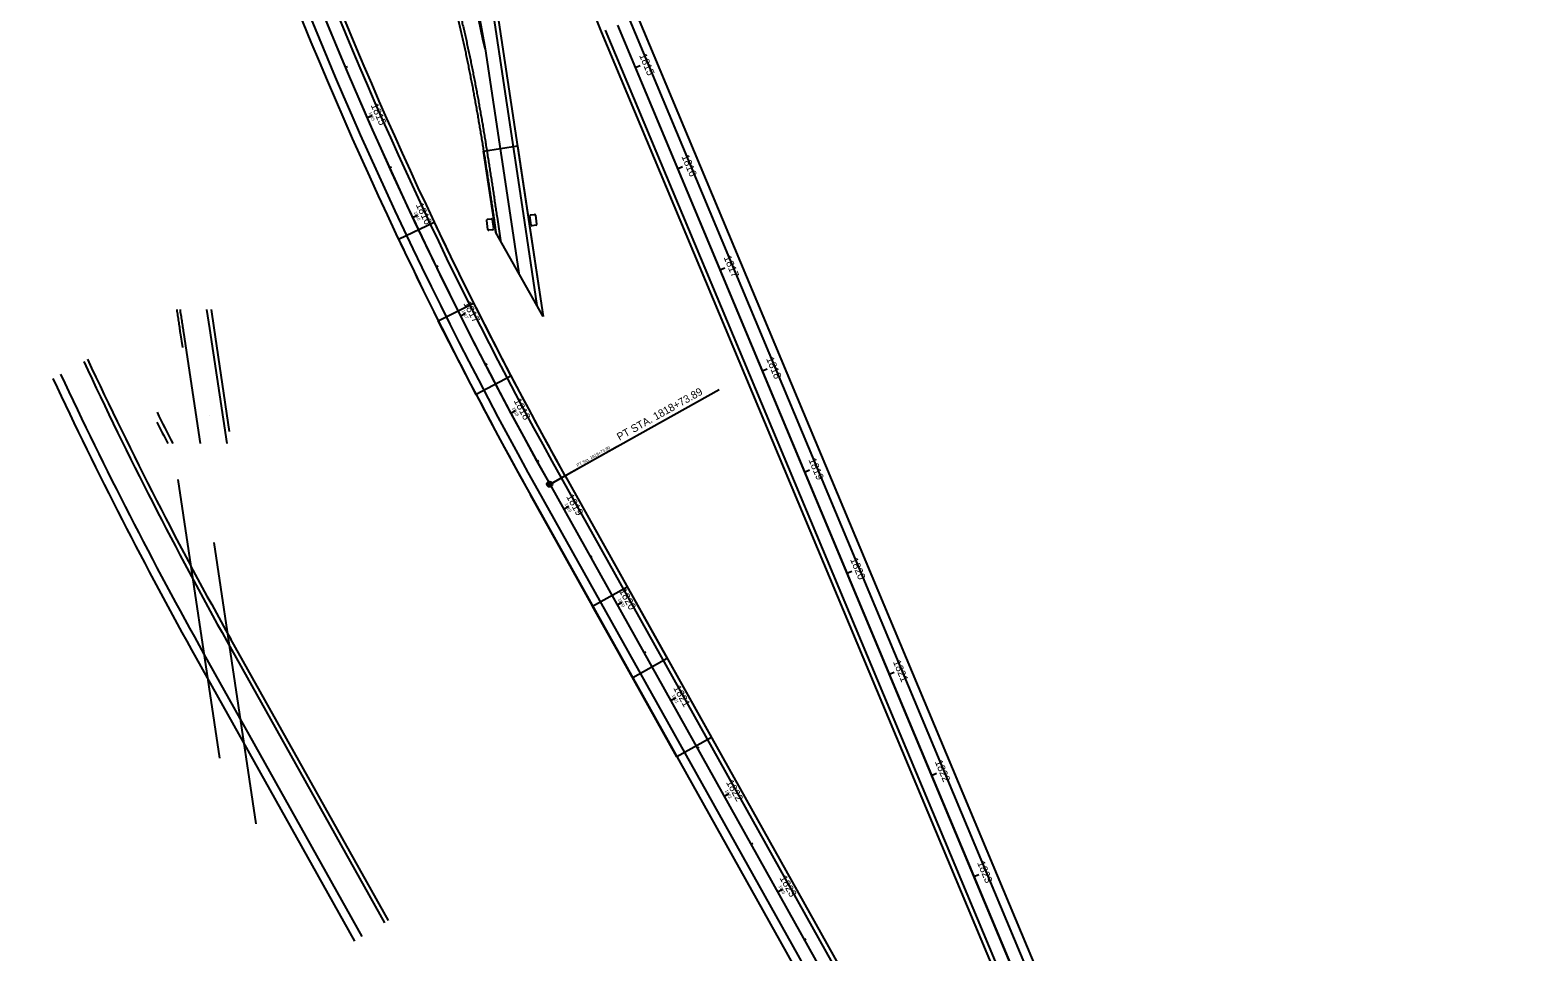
# Model space of a CAD drawing. Extents: x 8527 to 36635, y 12099 to 39012.
# Drawn here: x 20646 to 22022, y 33939 to 34779 of the extents above; entities that cross this region are included whole.
import ezdxf

# ---------------------------------------------------------------- set-up
doc = ezdxf.new("R2010")
doc.units = 0
for name, color, linetype in [('DR_P_Inlet_Protection', 7, 'Continuous'), ('GE_X_CL_20', 7, 'Continuous'), ('GK_Visualization', 7, 'Continuous'), ('MT_P_Dotted_Line', 7, 'Continuous'), ('MT_P_Edge_Line', 7, 'Continuous'), ('MT_P_Temp_Road', 7, 'Continuous'), ('MT_P_Text', 7, 'Continuous'), ('MT_P_Traffic_Attenuator', 7, 'Continuous'), ('PV_X_Shoulder', 7, 'Continuous'), ('SH_Cut_Line', 7, 'Continuous'), ('SH_Text', 7, 'Continuous')]:
    doc.layers.add(name, color=color, linetype=linetype)

msp = doc.modelspace()

# ---------------------------------------------------------------- linework, layer by layer
at = {"layer": 'DR_P_Inlet_Protection'}
for p, q in [((21182.2, 34784), (22003.5, 32822.1)), ((21120.4, 34365.1), (21585.9, 33532.8)), ((21120.4, 34365.1), (21585.9, 33532.8))]:
    msp.add_line(p, q, dxfattribs=at)
for start in [186.2167, 191.3361]:
    msp.add_arc((24529.9, 36271.9), 3906.5, start, 209.2167, dxfattribs=at)
at = {"layer": 'GE_X_CL_20'}
for p, q in [((20933.9, 34745.5), (20935.8, 34746.3)), ((20953.8, 34699.6), (20955.6, 34700.4)), ((20974.2, 34654), (20976, 34654.8)), ((20995.2, 34608.6), (20997, 34609.5)), ((21016.8, 34563.5), (21018.6, 34564.4)), ((21038.9, 34518.7), (21040.7, 34519.6)), ((21061.6, 34474.1), (21063.4, 34475.1)), ((21084.9, 34429.9), (21086.7, 34430.8)), ((21121.3, 34365.6), (21182.3, 34399.7)), ((21108.8, 34386), (21110.5, 34386.9)), ((21133.1, 34342.3), (21134.9, 34343.3)), ((21157.5, 34298.6), (21159.3, 34299.6)), ((21182, 34255), (21183.7, 34256)), ((21206.4, 34211.4), (21208.1, 34212.3)), ((21230.8, 34167.7), (21232.5, 34168.7)), ((21255.2, 34124.1), (21256.9, 34125.1)), ((21279.6, 34080.4), (21281.3, 34081.4)), ((21304, 34036.8), (21305.7, 34037.8)), ((21328.4, 33993.2), (21330.1, 33994.1)), ((21352.8, 33949.5), (21354.5, 33950.5))]:
    msp.add_line(p, q, dxfattribs=at)
msp.add_circle((21120.4, 34365.1), 1, dxfattribs=at)
at = {"layer": 'GK_Visualization'}
msp.add_line((21182.2, 34784), (21938.6, 32977.3), dxfattribs=at)
at = {"layer": 'MT_P_Dotted_Line'}
for p, q in [((21035.7, 34905.3), (21061.4, 34762.4)), ((21061.4, 34762.4), (21084.3, 34610.5)), ((21084.3, 34610.5), (21092.2, 34557.8))]:
    msp.add_line(p, q, dxfattribs=at)
msp.add_arc((20125.4, 34573.3), 954.9, 11.4213, 20.1187, dxfattribs=at)
at = {"layer": 'MT_P_Edge_Line'}
for p, q in [((21069.4, 34608.2), (21069.4, 34608.2)), ((21069.4, 34608.2), (21071.4, 34594.9)), ((20811.4, 34524.4), (20813.9, 34507.8)), ((20783.3, 34503.2), (20783.3, 34503.2)), ((20783.3, 34503.2), (20785.3, 34489.8)), ((20813.9, 34507.8), (20828.1, 34413.2)), ((20809.7, 34428), (20809.7, 34428)), ((20829.3, 34223.9), (20973, 33967.1)), ((20797.9, 34206.3), (20942.3, 33948.2))]:
    msp.add_line(p, q, dxfattribs=at)
for centre, radius, start, end in [((24224.9, 36122.9), 3890.5, 204.9928, 209.2167), ((24224.9, 36122.9), 3926.5, 205.0302, 209.2167), ((24243.8, 36166.8), 3890.5, 206.5019, 206.9732)]:
    msp.add_arc(centre, radius, start, end, dxfattribs=at)
msp.add_spline([(20780.1, 34524.4), (20780.5, 34521.9), (20780.9, 34519.2), (20781.3, 34516.5), (20781.7, 34513.9), (20782.1, 34511.2), (20782.5, 34508.5), (20782.9, 34505.8), (20783.3, 34503.2)], degree=3, dxfattribs=at)
at = {"layer": 'MT_P_Temp_Road'}
for p, q in [((21018.8, 34514.2), (21051, 34530.3)), ((21051, 34530.3), (21085.1, 34463.8)), ((20807.4, 34524.4), (20810, 34507.2)), ((21053.2, 34447.1), (21018.8, 34514.2)), ((20786.3, 34503.6), (20786.3, 34503.6)), ((20786.3, 34503.6), (20801.5, 34402.2)), ((20810, 34507.2), (20825.8, 34402.2)), ((21085.1, 34463.8), (21053.2, 34447.1)), ((20781, 34369.4), (20819.1, 34115.1)), ((20813.9, 34311.9), (20852.4, 34055.3)), ((21159.6, 34254), (21191, 34271.5)), ((21191, 34271.5), (21227.6, 34206.1)), ((21196.2, 34188.5), (21159.6, 34254)), ((21159.6, 34254), (21196.2, 34188.5)), ((20825.9, 34221.9), (20969.6, 33965)), ((20804.9, 34210.2), (20949.1, 33952.4)), ((21227.6, 34206.1), (21196.2, 34188.5))]:
    msp.add_line(p, q, dxfattribs=at)
for centre, radius, start, end in [((24226.8, 36123.6), 3896.5, 204.9949, 209.2125), ((24224.9, 36122.9), 3918.5, 205.0219, 209.2167), ((24245.6, 36167.5), 3896.5, 206.6166, 206.9403)]:
    msp.add_arc(centre, radius, start, end, dxfattribs=at)
msp.add_spline([(20783.1, 34524.4), (20783.4, 34522.3), (20783.9, 34519.6), (20784.3, 34517), (20784.7, 34514.3), (20785.1, 34511.6), (20785.5, 34509), (20785.9, 34506.3), (20786.3, 34503.6)], degree=3, dxfattribs=at)
at = {"layer": 'MT_P_Text'}
for p, q in [((21182.2, 34784), (21938.6, 32977.3)), ((20953.8, 34699.6), (20958.4, 34701.6)), ((20995.2, 34608.6), (20999.7, 34610.7)), ((21038.9, 34518.7), (21043.4, 34520.9)), ((21122.6, 34366.3), (21275.1, 34451.6)), ((21084.9, 34429.9), (21089.3, 34432.3)), ((21120.4, 34365.1), (21585.9, 33532.8)), ((21133.1, 34342.3), (21137.5, 34344.7)), ((21182, 34255), (21186.3, 34257.4)), ((21230.8, 34167.7), (21235.1, 34170.2)), ((21279.6, 34080.4), (21283.9, 34082.9)), ((21328.4, 33993.2), (21332.7, 33995.6))]:
    msp.add_line(p, q, dxfattribs=at)
msp.add_circle((21120.4, 34365.1), 2.5, dxfattribs=at)
msp.add_arc((24529.9, 36271.9), 3906.5, 186.2167, 209.2167, dxfattribs=at)
at = {"layer": 'MT_P_Traffic_Attenuator'}
for p, q in [((21067.1, 34832.4), (21100.1, 34612.8)), ((21200.6, 34791.7), (22022, 32829.9)), ((21167.4, 34777.8), (21988.8, 32816)), ((21100.1, 34612.8), (21114.3, 34518.3)), ((21134.4, 34372.9), (21599.8, 33540.6)), ((21102.9, 34355.3), (21568.4, 33523))]:
    msp.add_line(p, q, dxfattribs=at)
for centre, radius, start, end in [((24529.9, 36271.9), 3926.5, 191.3414, 209.2167), ((24529.9, 36271.9), 3890.5, 192.8663, 209.2167), ((28229, 37734.2), 7655.4, 198.78578, 202.71667)]:
    msp.add_arc(centre, radius, start, end, dxfattribs=at)
msp.add_spline([(21032.9, 34804.5), (21033.6, 34801.8), (21034.3, 34799.2), (21034.9, 34796.6), (21035.6, 34794), (21036.2, 34791.4), (21036.9, 34788.8), (21037.5, 34786.2), (21038.1, 34783.5), (21038.7, 34780.9), (21039.4, 34778.3), (21040, 34775.7), (21040.6, 34773), (21041.1, 34770.4), (21041.7, 34767.8), (21042.3, 34765.1), (21042.9, 34762.5), (21043.5, 34759.9), (21044, 34757.2), (21044.6, 34754.6), (21045.1, 34751.9), (21045.7, 34749.3), (21046.2, 34746.7), (21046.7, 34744), (21047.3, 34741.4), (21047.8, 34738.7), (21048.3, 34736.1), (21048.8, 34733.4), (21049.3, 34730.8), (21049.9, 34728.1), (21050.4, 34725.5), (21050.9, 34722.8), (21051.3, 34720.2), (21051.8, 34717.5), (21052.3, 34714.9), (21052.8, 34712.2), (21053.3, 34709.6), (21053.7, 34706.9), (21054.2, 34704.3), (21054.7, 34701.6), (21055.1, 34698.9), (21055.6, 34696.3), (21056.1, 34693.6), (21056.5, 34691), (21057, 34688.3), (21057.4, 34685.6), (21057.8, 34683), (21058.3, 34680.3), (21058.7, 34677.6), (21059.2, 34675), (21059.6, 34672.3), (21060, 34669.6), (21060.4, 34667), (21060.9, 34664.3), (21061.3, 34661.6), (21061.7, 34659), (21062.1, 34656.3), (21062.5, 34653.6), (21063, 34651), (21063.4, 34648.3), (21063.8, 34645.6), (21064.2, 34643), (21064.6, 34640.3), (21065, 34637.6), (21065.4, 34635), (21065.8, 34632.3), (21066.2, 34629.6), (21066.6, 34626.9), (21067, 34624.3), (21067.4, 34621.6), (21067.8, 34618.9), (21068.2, 34616.3), (21068.6, 34613.6), (21069, 34610.9), (21069.4, 34608.2)], degree=3, dxfattribs=at)
at = {"layer": 'PV_X_Shoulder'}
for points in [[(21103.1, 34610.8), (21106.4, 34611.3)], [(21107.4, 34610.6), (21108.5, 34602.3)], [(21064.1, 34597.6), (21062.9, 34605.8)], [(21063.6, 34606.8), (21066.9, 34607.2)], [(21068.3, 34597.3), (21065, 34596.9)], [(21067.9, 34606.5), (21069, 34598.3)], [(21103.6, 34601.6), (21102.4, 34609.9)], [(21107.8, 34601.4), (21104.5, 34600.9)]]:
    msp.add_lwpolyline(points, dxfattribs=at)
for centre, start, end in [((21103.3, 34610), 98, 188), ((21106.6, 34610.5), 8, 98), ((21063.7, 34605.9), 98, 188), ((21064.9, 34597.7), 188, 278), ((21067, 34606.4), 8, 98), ((21068.2, 34598.1), 278, 8), ((21104.4, 34601.7), 188, 278), ((21107.7, 34602.2), 278, 8)]:
    msp.add_arc(centre, 0.833, start, end, dxfattribs=at)
at = {"layer": 'SH_Cut_Line'}
for p, q in [((21198.4, 34745.2), (21203.1, 34747.1)), ((21237.1, 34653), (21241.7, 34654.9)), ((21275.7, 34560.7), (21280.3, 34562.7)), ((21314.3, 34468.5), (21318.9, 34470.4)), ((21352.9, 34376.2), (21357.5, 34378.2)), ((21391.5, 34284), (21396.1, 34285.9)), ((21430.1, 34191.8), (21434.8, 34193.7)), ((21468.8, 34099.5), (21473.4, 34101.4)), ((21507.4, 34007.3), (21512, 34009.2))]:
    msp.add_line(p, q, dxfattribs=at)
at = {"layer": 'SH_Text'}
for p, q in [((21063.2, 34831.8), (21096.1, 34612.2)), ((21171.1, 34779.4), (21992.5, 32817.5)), ((21193.3, 34788.7), (22014.6, 32826.8)), ((21060.1, 34668.9), (21090.9, 34673.8)), ((21071.4, 34594.9), (21060.1, 34668.9)), ((21090.9, 34673.8), (21114.3, 34518.3)), ((21096.1, 34612.2), (21108.8, 34528.1)), ((20982.5, 34588.7), (21015, 34604.2)), ((21072.4, 34608.7), (21072.4, 34608.7)), ((21072.4, 34608.7), (21075.6, 34587.5)), ((21114.3, 34518.3), (21071.4, 34594.9)), ((21130.9, 34370.9), (21596.3, 33538.6)), ((21134.4, 34372.9), (21267.9, 34134.1)), ((21236.5, 34116.5), (21102.9, 34355.3)), ((21109.9, 34359.2), (21575.4, 33526.9)), ((21267.9, 34134.1), (21236.5, 34116.5))]:
    msp.add_line(p, q, dxfattribs=at)
for centre, radius, start, end in [((24529.9, 36271.9), 3918.5, 191.3361, 209.2167), ((24531.8, 36272.6), 3896.5, 192.8705, 209.2125), ((24529.9, 36271.9), 3890.5, 205.3829, 209.2167), ((24529.9, 36271.9), 3926.5, 205.3829, 209.2167)]:
    msp.add_arc(centre, radius, start, end, dxfattribs=at)
msp.add_spline([(21035.8, 34805.2), (21036.5, 34802.6), (21037.2, 34800), (21037.8, 34797.4), (21038.5, 34794.7), (21039.1, 34792.1), (21039.8, 34789.5), (21040.4, 34786.9), (21041, 34784.2), (21041.7, 34781.6), (21042.3, 34779), (21042.9, 34776.3), (21043.5, 34773.7), (21044.1, 34771.1), (21044.7, 34768.4), (21045.2, 34765.8), (21045.8, 34763.1), (21046.4, 34760.5), (21047, 34757.8), (21047.5, 34755.2), (21048.1, 34752.6), (21048.6, 34749.9), (21049.2, 34747.3), (21049.7, 34744.6), (21050.2, 34742), (21050.7, 34739.3), (21051.3, 34736.7), (21051.8, 34734), (21052.3, 34731.4), (21052.8, 34728.7), (21053.3, 34726), (21053.8, 34723.4), (21054.3, 34720.7), (21054.8, 34718.1), (21055.3, 34715.4), (21055.8, 34712.8), (21056.2, 34710.1), (21056.7, 34707.4), (21057.2, 34704.8), (21057.6, 34702.1), (21058.1, 34699.4), (21058.6, 34696.8), (21059, 34694.1), (21059.5, 34691.5), (21059.9, 34688.8), (21060.4, 34686.1), (21060.8, 34683.5), (21061.2, 34680.8), (21061.7, 34678.1), (21062.1, 34675.5), (21062.5, 34672.8), (21063, 34670.1), (21063.4, 34667.5), (21063.8, 34664.8), (21064.3, 34662.1), (21064.7, 34659.4), (21065.1, 34656.8), (21065.5, 34654.1), (21065.9, 34651.4), (21066.3, 34648.8), (21066.7, 34646.1), (21067.2, 34643.4), (21067.6, 34640.7), (21068, 34638.1), (21068.4, 34635.4), (21068.8, 34632.7), (21069.2, 34630.1), (21069.6, 34627.4), (21070, 34624.7), (21070.4, 34622), (21070.8, 34619.4), (21071.2, 34616.7), (21071.6, 34614), (21072, 34611.4), (21072.4, 34608.7)], degree=3, dxfattribs=at)

# ---------------------------------------------------------------- texts
at = {"layer": 'GE_X_CL_20'}
for s, rotation, p in [('1815', 293.7329, (20955.1, 34704.1)), ('1816', 295.1996, (20996.4, 34613.2)), ('1817', 296.6662, (21040, 34523.3)), ('1818', 298.1329, (21085.9, 34434.4)), ('PT Sta. 1818+73.89', 29.2167, (21145.9, 34380.9)), ('1819', 299.2167, (21134, 34346.9)), ('1820', 299.2167, (21182.5, 34260.1)), ('1821', 299.2167, (21231.6, 34172.4)), ('1822', 299.2167, (21280.2, 34085.5)), ('1823', 299.2167, (21329, 33998.3))]:
    msp.add_text(s, height=2.8, rotation=rotation, dxfattribs=at).set_placement(p)
at = {"layer": 'MT_P_Text'}
for s, rotation, p in [('1815', 293.7329, (20957, 34710.9)), ('1816', 295.1996, (20998.1, 34620)), ('1817', 296.6662, (21041.5, 34530.2)), ('PT STA. 1818+73.89', 29.2167, (21184.1, 34404.7)), ('1818', 298.1329, (21087.4, 34441.3)), ('1819', 299.2167, (21135.3, 34353.8)), ('1820', 299.2167, (21183.4, 34267.8)), ('1821', 299.2167, (21232.9, 34179.3)), ('1822', 299.2167, (21281.1, 34093.1)), ('1823', 299.2167, (21329.9, 34005.9))]:
    msp.add_text(s, height=7, rotation=rotation, dxfattribs=at).set_placement(p)
at = {"layer": 'SH_Cut_Line'}
for s, p in [('1815', (21201.9, 34756.4)), ('1816', (21240.5, 34664.2)), ('1817', (21279, 34572.1)), ('1818', (21317.8, 34479.6)), ('1819', (21356.4, 34387.4)), ('1820', (21394.4, 34296.5)), ('1821', (21433.5, 34203.1)), ('1822', (21471.7, 34111.9)), ('1823', (21510.3, 34019.7))]:
    msp.add_text(s, height=7, rotation=292.7167, dxfattribs=at).set_placement(p)

doc.saveas('drawing.dxf')
